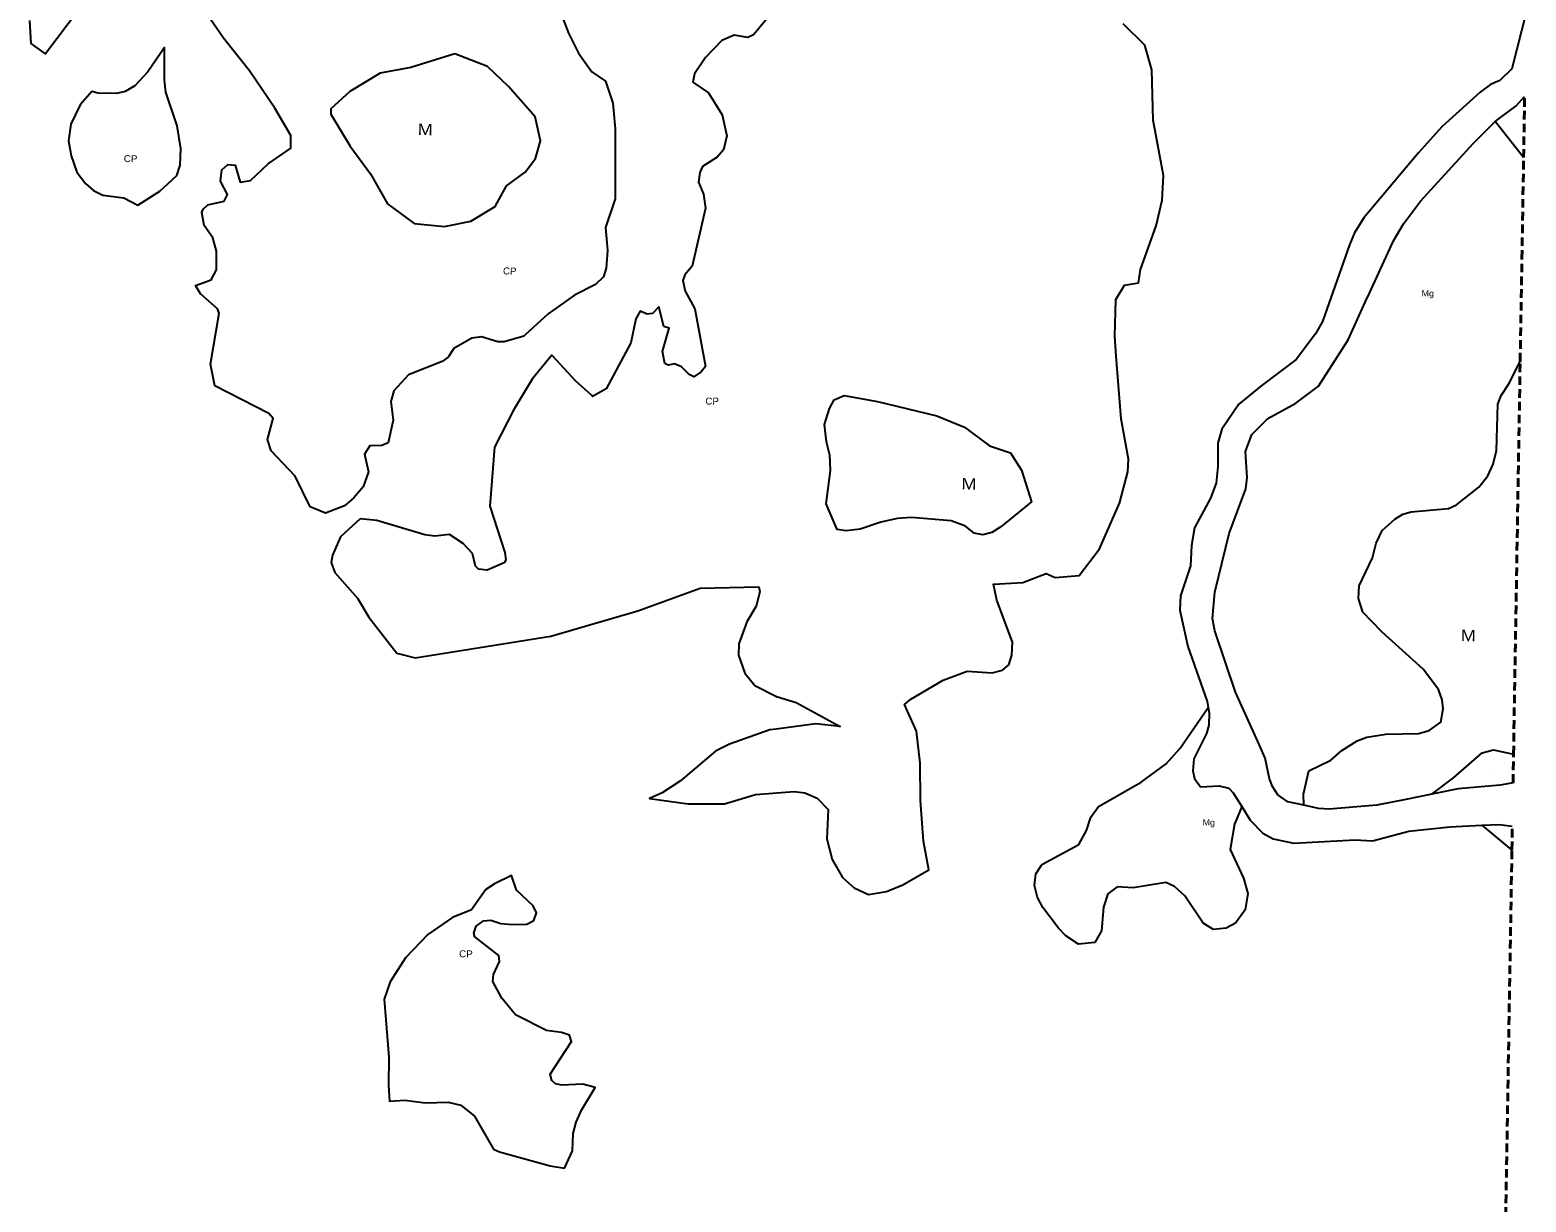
# Model space of a CAD drawing. Extents: x 713589 to 726391, y 7177764 to 7191819.
# Drawn here: x 724849 to 726223, y 7180574 to 7181651 of the extents above; entities that cross this region are included whole.
import ezdxf
from ezdxf.enums import TextEntityAlignment as Align

# ---------------------------------------------------------------- set-up
doc = ezdxf.new("R2010")
doc.units = 0
doc.header["$LTSCALE"] = 2.6
doc.linetypes.add('MEDIUM_DASHED', pattern=[4.5, 3, -1.5])
doc.layers.add('63', color=7, linetype='Continuous', lineweight=25)

msp = doc.modelspace()

# ---------------------------------------------------------------- linework, layer by layer
at = {"layer": '63', "linetype": 'MEDIUM_DASHED', "lineweight": 40}
for p, q in [((726220.77, 7181533.89), (726221.72, 7181590.19)), ((726211.51, 7180985.76), (726217.61, 7181346.65)), ((726211.07, 7180959.46), (726211.51, 7180985.76)), ((726210.02, 7180897.64), (726210.39, 7180919.67))]:
    msp.add_line(p, q, dxfattribs=at)
at = {"layer": '63'}
for p, q in [((726220.77, 7181533.89), (726194.7, 7181567.11)), ((726182.42, 7180920.47), (726210.02, 7180897.64))]:
    msp.add_line(p, q, dxfattribs=at)
for points in [[(724915.96, 7181699.68), (724863.01, 7181629.27), (724850, 7181638.87), (724848.77, 7181659.9)], [(725541.34, 7181680.57), (725513.36, 7181646.67), (725508.07, 7181644.41), (725495.78, 7181646.57), (725484.38, 7181641.49), (725469.4, 7181625.79), (725459.16, 7181610.95), (725457.81, 7181603.13), (725472.09, 7181593.45), (725484.75, 7181573.16), (725489.04, 7181553.94), (725485.76, 7181541.09), (725479.94, 7181534.36), (725466.6, 7181525.64), (725464.12, 7181520.33), (725462.77, 7181511.4), (725467.58, 7181500.27), (725469.32, 7181487.44), (725457.06, 7181434.1), (725450.41, 7181426.26), (725448.49, 7181420.95), (725450.49, 7181411.2), (725459.5, 7181395.07), (725469.28, 7181341.85), (725465.4, 7181337.09), (725458.45, 7181332.59), (725454.26, 7181334.52), (725447.24, 7181341.73), (725440.81, 7181344.48), (725434.96, 7181343.34), (725431.89, 7181344.71), (725429.87, 7181355.86), (725435.9, 7181377.09), (725431.14, 7181378.74), (725426.3, 7181396.84), (725420.48, 7181390.67), (725415.74, 7181390.09), (725409.31, 7181392.84), (725405.17, 7181385.85), (725400.82, 7181363.79), (725378.08, 7181321.33), (725365.53, 7181314.53), (725364.74, 7181315.53), (725350.16, 7181328.56), (725328.84, 7181351.87), (725328.31, 7181352.32), (725310.17, 7181330.47), (725293.03, 7181301.93), (725275.65, 7181267.81), (725271.2, 7181213.67), (725285.1, 7181171.08), (725285.98, 7181164.39), (725284.32, 7181161.59), (725268.74, 7181154.81), (725260.92, 7181155.88), (725258.12, 7181158.66), (725255.26, 7181170.08), (725246.57, 7181179.23), (725234.25, 7181187.53), (725220.59, 7181186.06), (725211.38, 7181187.41), (725167.52, 7181200.56), (725152.12, 7181202.09), (725133.94, 7181185.47), (725126.82, 7181168.77), (725125.45, 7181161.92), (725128.73, 7181152.61), (725149.54, 7181129.05), (725160.22, 7181111.52), (725185.69, 7181078.64), (725202.67, 7181074.26), (725327.3, 7181094.22), (725407.01, 7181117.49), (725464.53, 7181138.29), (725518.37, 7181139.61), (725519.16, 7181135.02), (725515.89, 7181121.62), (725507.32, 7181107.35), (725499.9, 7181087.22), (725499.67, 7181076.62), (725505.34, 7181060.2)], [(725232.99, 7181350.69), (725227.43, 7181346.48), (725196.54, 7181334.32), (725183.04, 7181319.65), (725180.31, 7181309.68), (725182.36, 7181292.59), (725177.82, 7181271.92), (725172.16, 7181269.47), (725161.1, 7181269.14), (725156.21, 7181261.39), (725159.74, 7181245.05), (725154.89, 7181231.45), (725146.3, 7181221.17), (725137.6, 7181213.97), (725120.16, 7181207.36), (725106.27, 7181212.96), (725092.55, 7181241.15), (725070.38, 7181264.46), (725066.98, 7181274.76), (725072.17, 7181294.31), (725068.24, 7181298.75), (725018.74, 7181324.14), (725014.72, 7181344.2), (725022.56, 7181391.1), (725021.14, 7181395), (725005.44, 7181408.86), (725000.94, 7181416.37), (725015.14, 7181421.74), (725020.11, 7181430.7), (725020.01, 7181447.99), (725016.88, 7181460.24), (725008.73, 7181471.63), (725006.71, 7181483.62), (725007.81, 7181486.69), (725012.25, 7181490.62), (725027.29, 7181493.77), (725030.33, 7181499.92), (725023.85, 7181512.16), (725025.18, 7181522.77), (725030.46, 7181527.54), (725037.15, 7181527.01), (725041.98, 7181511.42), (725051.46, 7181512.87), (725067.55, 7181528.3), (725088.39, 7181542.64), (725088.33, 7181554.35), (725073.68, 7181579.37), (725050.35, 7181613.55), (725026.48, 7181643.54), (725005.39, 7181674.39)], [(725335.56, 7181669.13), (725343.49, 7181648.16), (725352.61, 7181629.8), (725364.88, 7181612.76), (725377.38, 7181604.09)], [(726223.03, 7181667.38), (726209.86, 7181615.54), (726198.87, 7181604.77), (726190.27, 7181601.07), (726180.82, 7181594.18), (726145.56, 7181562.21), (726124.09, 7181538.19), (726074.12, 7181478.64), (726065.28, 7181464.82), (726060.72, 7181453.77), (726036.02, 7181383.37), (726029.58, 7181371.92), (726011.92, 7181348.34), (725979.27, 7181323.84), (725959.11, 7181307.26), (725943.47, 7181284.34), (725940.01, 7181271.66), (725939.96, 7181250), (725938.24, 7181234.86), (725933.28, 7181220.99), (725918.58, 7181193.67), (725915.81, 7181177.51), (725914.87, 7181158.69), (725905.76, 7181131.18), (725905.06, 7181118.19), (725912.33, 7181084.85), (725930.08, 7181034.28), (725931.11, 7181028.78)], [(725505.34, 7181060.2), (725514.61, 7181048.81), (725534.47, 7181038.88), (725552.63, 7181033.12), (725593.03, 7181011.04), (725570.71, 7181013.76), (725534.15, 7181008.81), (725528.44, 7181008.04), (725491.32, 7180995.1), (725478.44, 7180988.43), (725446.32, 7180961.29), (725429.65, 7180950.33), (725417.83, 7180945.11), (725453.53, 7180940.26), (725486.67, 7180940.26), (725515.16, 7180948.74), (725550.8, 7180951.5), (725550.88, 7180951.49), (725560.63, 7180950.38), (725571.86, 7180945.44), (725581.99, 7180935.03), (725580.89, 7180907.92), (725585.54, 7180889.02), (725595.12, 7180872.31), (725605.8, 7180862.99), (725618.95, 7180856.96), (725635.66, 7180859.42), (725650.45, 7180865.72), (725674.39, 7180879.38), (725669.67, 7180905.8), (725666.67, 7180943.16), (725666.49, 7180977.47), (725663.26, 7181007.01), (725652.01, 7181031.52), (725657.8, 7181036.18), (725687.64, 7181053.63), (725709.63, 7181062.12), (725732.6, 7181060.48), (725741.98, 7181062.95), (725747.81, 7181067.72), (725750.83, 7181076.76), (725751.23, 7181088.57), (725736.89, 7181127.35), (725733.91, 7181142.09), (725760.83, 7181143.37), (725782.11, 7181151.76), (725790.6, 7181148.2), (725812.6, 7181149.93), (725831.32, 7181174.39), (725849.79, 7181216.96), (725849.96, 7181217.36), (725857.18, 7181245.05), (725857.73, 7181256.92), (725851.25, 7181293.99), (725846.43, 7181351.51), (725845.33, 7181369.86), (725846.16, 7181403.64), (725854.2, 7181416.61), (725866.98, 7181418.98), (725868.81, 7181431.12), (725883.34, 7181471.11), (725888.82, 7181494.84), (725890.1, 7181517.58), (725880.53, 7181568.25), (725879.26, 7181614.54), (725872.87, 7181637.18), (725852.97, 7181656.73)], [(725377.38, 7181604.09), (725384.28, 7181583.86), (725386.46, 7181560.25), (725386.25, 7181496.01), (725377.37, 7181469.84), (725379.16, 7181448.46), (725378.14, 7181432.19), (725375.67, 7181424.46), (725368.18, 7181417.44), (725348.89, 7181407.48), (725324.72, 7181390.52), (725303.62, 7181371.12), (725302.34, 7181369.94), (725284.23, 7181364.64), (725278.65, 7181364.7), (725263.66, 7181369.27), (725254.74, 7181368.01), (725238.06, 7181358.44), (725232.99, 7181350.69)], [(726194.7, 7181567.11), (726213.9, 7181581.46), (726221.72, 7181590.19)], [(726018.85, 7180938.77), (726004.05, 7180942.02), (725995.11, 7180948.39), (725990.16, 7180955.93), (725987.23, 7180963.06), (725983.48, 7180982.05), (725978.02, 7180994.01), (725956.25, 7181042.82), (725937.09, 7181099.04), (725935.05, 7181110.43), (725937.05, 7181134.64), (725950.21, 7181188.48), (725965.75, 7181229.43), (725966.87, 7181239.89), (725965.46, 7181263.78), (725971.27, 7181279.62), (725985.7, 7181294.07), (726011.64, 7181308.26), (726032.28, 7181323.81), (726059.72, 7181366.38), (726075.62, 7181401.66), (726079.11, 7181409.28), (726101.17, 7181457.46), (726110.49, 7181472.96), (726126.16, 7181493.8), (726174.52, 7181546.92), (726194.7, 7181567.11)], [(726018.85, 7180938.77), (726018.63, 7180948.89), (726023.34, 7180970.53), (726043.71, 7180980.23), (726053.88, 7180989.28), (726067.96, 7180998.05), (726076.65, 7181001.39), (726094.35, 7181004.17), (726124.37, 7181004.9), (726133.97, 7181007.64), (726144.74, 7181015.2), (726146.79, 7181027.52), (726145.86, 7181035.62), (726142.51, 7181045.21), (726128.62, 7181063.77), (726090.64, 7181098.13), (726073.14, 7181116.37), (726069.19, 7181128.66), (726069.74, 7181140.37), (726081.93, 7181166.25), (726085.48, 7181179.77), (726090.83, 7181191.2), (726102.5, 7181201.76), (726109.68, 7181206.3), (726117.48, 7181208.44), (726151.69, 7181211.59), (726159.18, 7181214.92), (726179.53, 7181231.22), (726187.89, 7181241.47), (726192.95, 7181252.3), (726195.9, 7181264.92), (726197.21, 7181307.26), (726200.18, 7181315.38), (726207.34, 7181325.92), (726217.61, 7181346.65)], [(725961.82, 7180937.83), (725955.1, 7180921.59), (725951.3, 7180898.16), (725963.42, 7180871.79), (725967.39, 7180857.69), (725965.05, 7180842.67), (725956.09, 7180830.62), (725947.41, 7180825.78), (725936, 7180824.53), (725926.37, 7180830.49), (725909.45, 7180855.64), (725900.1, 7180864.31), (725892.28, 7180867.87), (725861.98, 7180862.94), (725847.56, 7180863.78), (725838.88, 7180857.43), (725835.03, 7180845.11), (725833.03, 7180823.48), (725826.77, 7180812.64), (725812.06, 7180811.08), (725800.32, 7180818.83), (725793.68, 7180826.01), (725779.19, 7180844.86), (725774.34, 7180854.15), (725771.59, 7180864.95), (725772.75, 7180875.76), (725777.95, 7180883.64), (725778.71, 7180884.79), (725812.12, 7180902.81), (725819.41, 7180915.6), (725823.26, 7180927.92), (725830.43, 7180937.56), (725869.36, 7180959.95), (725892.4, 7180976.86), (725905.25, 7180991.33), (725931.11, 7181028.78)], [(725931.11, 7181028.78), (725932.07, 7181023.63), (725931.75, 7181012.42), (725929.64, 7181004.85), (725917.9, 7180981.58), (725916.91, 7180970.48), (725918.51, 7180963.37), (725923.93, 7180955.83), (725940.98, 7180956.79), (725950.03, 7180954.6), (725954.1, 7180950.37), (725961.82, 7180937.83)], [(726136.36, 7180949.02), (726156.38, 7180963.91), (726182.7, 7180987.14), (726193.19, 7180989.89), (726211.51, 7180985.76)], [(726136.36, 7180949.02), (726112.7, 7180944.18), (726085.99, 7180939.02), (726042.18, 7180935.12), (726032.28, 7180935.81), (726018.85, 7180938.77)], [(726211.07, 7180959.46), (726211.06, 7180959.46), (726199.11, 7180957.13), (726160.74, 7180954), (726136.36, 7180949.02)], [(725961.82, 7180937.83), (725969.7, 7180925.02), (725981.2, 7180913.19), (725990.81, 7180908.02), (726009.59, 7180903.84), (726065.93, 7180907.02), (726082.07, 7180906.25), (726115.33, 7180915.16), (726153.01, 7180919.04), (726182.42, 7180920.47)], [(726182.42, 7180920.47), (726198.22, 7180921.24), (726210.39, 7180919.67)]]:
    msp.add_lwpolyline(points, dxfattribs=at)
for points in [[(724983.8, 7181517.63), (724986.65, 7181526.93), (724987.41, 7181542.19), (724984.16, 7181563.13), (724973.54, 7181594), (724972.38, 7181605.03), (724972.45, 7181635.16), (724957.09, 7181612.83), (724945.14, 7181599.86), (724936.19, 7181594.83), (724928.16, 7181592.8), (724911.38, 7181593.21), (724905.64, 7181594.69), (724894.94, 7181582.33), (724886.48, 7181564.8), (724884.15, 7181549.45), (724886.64, 7181535.61), (724891.93, 7181520.58), (724899.8, 7181510.02), (724907.27, 7181503.56), (724915.85, 7181499.51), (724935.11, 7181497.11), (724947.78, 7181490.18), (724968.03, 7181503.14)], [(725161.59, 7181519.05), (725177.09, 7181491.52), (725201.73, 7181473.52), (725229.64, 7181470.61), (725253.88, 7181475.48), (725276.11, 7181488.99), (725286.61, 7181508.02), (725303.55, 7181520.66), (725313.25, 7181533.26), (725317.9, 7181549.47), (725312.76, 7181571.47), (725288.34, 7181599.23), (725269, 7181617.53), (725239.09, 7181629.36), (725198.71, 7181616.87), (725170.57, 7181611.42), (725142.49, 7181594.81), (725125.29, 7181578.82), (725125.04, 7181573.8), (725142.77, 7181544.33)], [(725584.16, 7181246.34), (725583.53, 7181260.57), (725580.3, 7181272.82), (725578.63, 7181288.8), (725583.11, 7181303.52), (725587.34, 7181311.35), (725596.71, 7181315.31), (725627.24, 7181309.8), (725681.88, 7181296.53), (725707.32, 7181286.25), (725730.29, 7181269.18), (725749.38, 7181262.77), (725759.51, 7181246.84), (725768.8, 7181217.49), (725740.46, 7181194.57), (725732.21, 7181189.51), (725724.04, 7181187.23), (725716.04, 7181188.86), (725708.1, 7181195.42), (725694.87, 7181200.18), (725658.41, 7181203.24), (725645.67, 7181202.33), (725630.44, 7181198.9), (725611.51, 7181192.66), (725598.6, 7181191.1), (725590.13, 7181192.17), (725580.24, 7181215.83)], [(725292.18, 7180829.1), (725305.05, 7180829.55), (725311.63, 7180832.83), (725314.09, 7180839.86), (725310.9, 7180846.26), (725295.75, 7180860.78), (725291, 7180874.36), (725275.59, 7180866.47), (725267.49, 7180861.33), (725254.43, 7180842.73), (725236.89, 7180835.66), (725214.38, 7180820.2), (725193.86, 7180798.61), (725179.76, 7180776.5), (725174.27, 7180760.57), (725178.46, 7180707.32), (725178.04, 7180681.65), (725178.99, 7180666.83), (725192.99, 7180667.7), (725212.07, 7180665.5), (725232.98, 7180666.14), (725244.48, 7180663.12), (725257.26, 7180653.17), (725274.73, 7180622.77), (725279.97, 7180620.22), (725326.71, 7180607.5), (725339.73, 7180605.34), (725347.1, 7180621.38), (725347.74, 7180637.35), (725350.57, 7180647.49), (725355.32, 7180658.62), (725367.83, 7180679.62), (725356.61, 7180682.54), (725337.43, 7180681.64), (725331.68, 7180682.73), (725328.21, 7180685.93), (725326.66, 7180691.86), (725346.3, 7180721.81), (725344.29, 7180727.47), (725337.08, 7180730.12), (725323.29, 7180731.85), (725294.9, 7180746.1), (725282.12, 7180761.63), (725274.09, 7180776.88), (725274.64, 7180783.18), (725279.94, 7180795.23), (725279.48, 7180800.89), (725257.39, 7180817.78), (725256.48, 7180821.25), (725258.67, 7180827.82), (725265.34, 7180832.66), (725272.09, 7180833.3), (725281.41, 7180830.19)]]:
    msp.add_lwpolyline(points, close=True, dxfattribs=at)
at = {"layer": '63', "linetype": 'MEDIUM_DASHED', "lineweight": 40}
for points in [[(726217.61, 7181346.65), (726219.2, 7181441.15), (726220.77, 7181533.89)], [(726191.19, 7179783.66), (726196.13, 7180075.65), (726203.16, 7180491.41), (726210.02, 7180897.64)]]:
    msp.add_lwpolyline(points, dxfattribs=at)

# ---------------------------------------------------------------- texts
at = {"layer": '63'}
for s, height, width, p in [('M', 0.52, 1.2, (726203.52, 7181568.17)), ('M', 10.4, 1.2, (725211.84, 7181554.59)), ('CP', 6.4, 1.05, (724941.2, 7181529.77)), ('CP', 6.4, 1.05, (725289.46, 7181426.53)), ('Mg', 5.6, 1.1, (726132.66, 7181406.46)), ('CP', 6.4, 1.05, (725475.34, 7181306.96)), ('M', 10.4, 1.2, (725711.24, 7181228.91)), ('M', 10.4, 1.2, (726169.9, 7181089.58)), ('Mg', 0.28, 1.1, (726193.61, 7180967.67)), ('Mg', 5.6, 1.1, (725931.51, 7180920.26)), ('Mg', 0.28, 1.1, (726203.76, 7180911.22)), ('CP', 6.4, 1.05, (725249.22, 7180799.09))]:
    msp.add_text(s, height=height, rotation=359.062, dxfattribs=dict(at, width=width)).set_placement(p, align=Align.CENTER)

doc.saveas('drawing.dxf')
